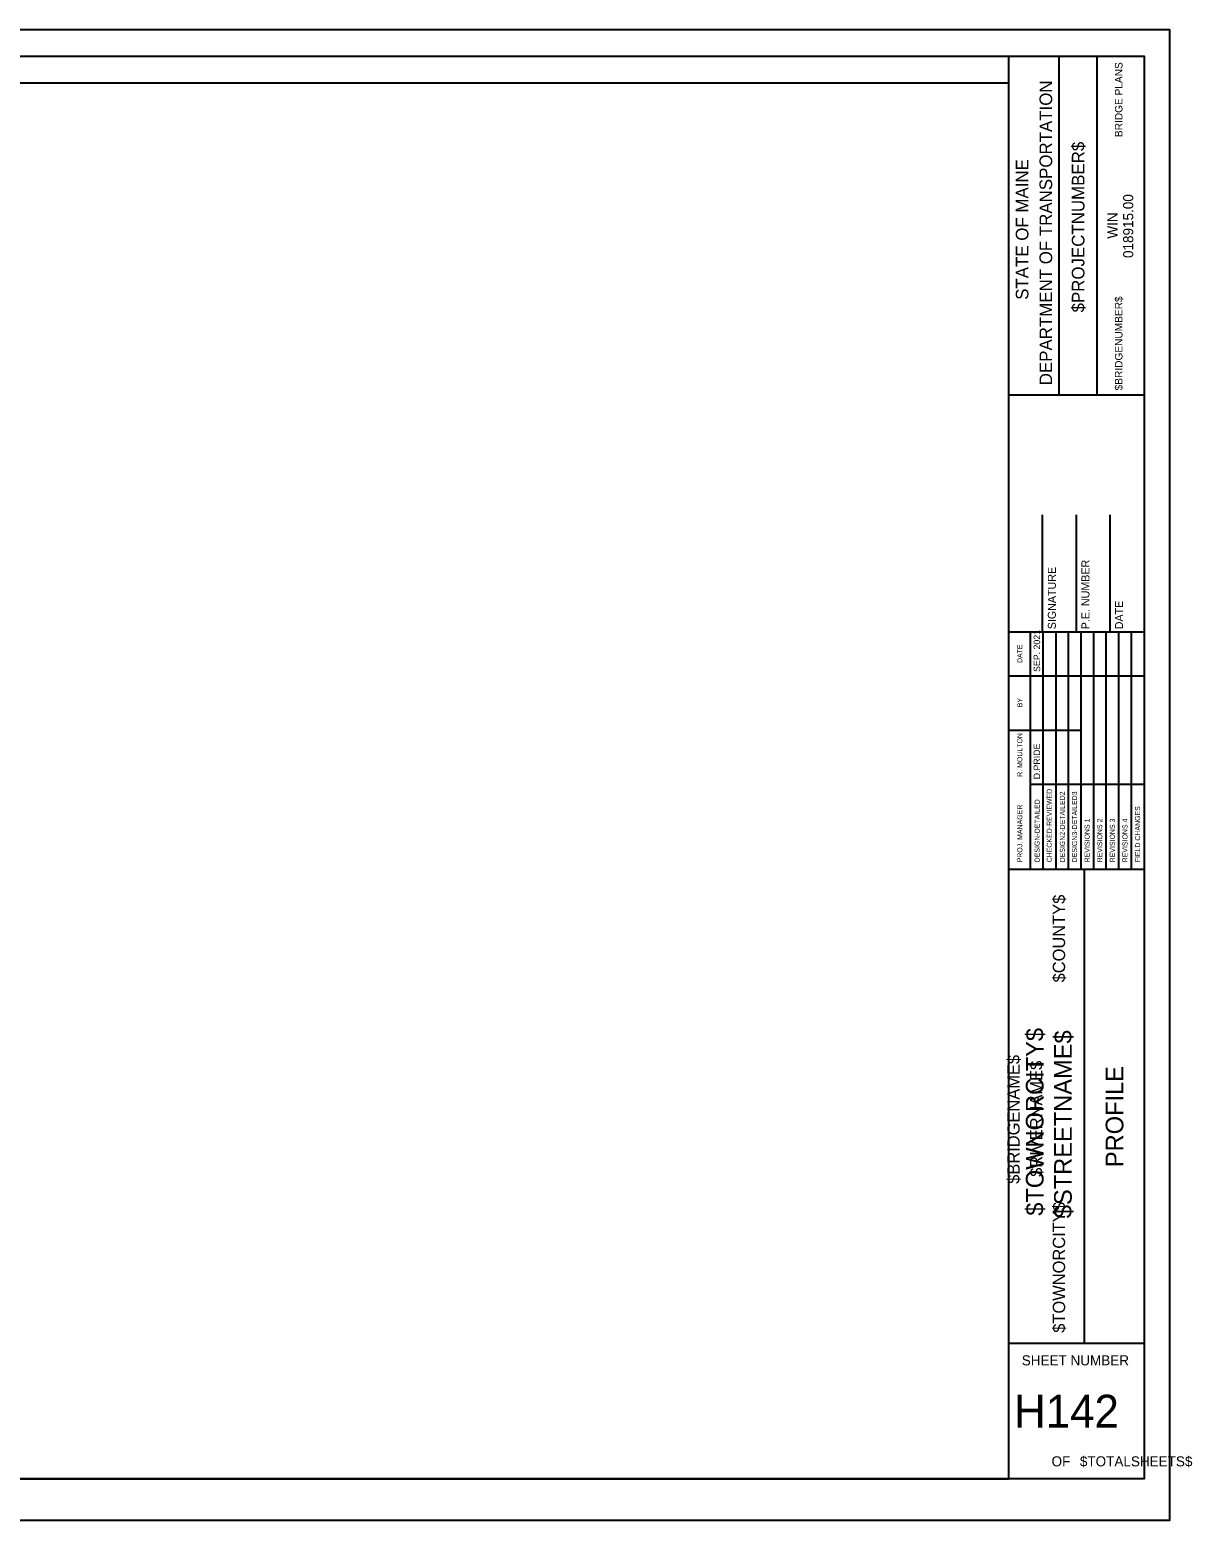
# Model space of a CAD drawing. Extents: x 11800 to 12658, y 9985 to 10535.
# Drawn here: x 12229 to 12658, y 9985 to 10535 of the extents above; entities that cross this region are included whole.
import ezdxf

# ---------------------------------------------------------------- set-up
doc = ezdxf.new("R2010")
doc.units = 0
for name, color, linetype in [('BORDER', 7, 'Continuous'), ('BRIDGE_TITLE', 7, 'Continuous'), ('CLIPS', 7, 'Continuous'), ('HIGHWAY_TITLE', 7, 'Continuous'), ('PLOT BOUNDARY', 7, 'Continuous')]:
    doc.layers.add(name, color=color, linetype=linetype)

msp = doc.modelspace()

# ---------------------------------------------------------------- linework, layer by layer
at = {"layer": 'BORDER'}
for p, q in [((12590.42, 10000), (12590.42, 10525)), ((12609.06, 10399.99), (12609.06, 10524.99)), ((12623.03, 10399.99), (12623.03, 10524.99)), ((12590.42, 10399.97), (12640.42, 10399.97)), ((12602.92, 10312.51), (12602.92, 10355.75)), ((12615.42, 10312.51), (12615.42, 10355.75)), ((12627.92, 10312.51), (12627.92, 10355.75)), ((12590.42, 10312.51), (12640.42, 10312.51)), ((12590.42, 10225.01), (12640.42, 10225.01)), ((12618.37, 10050.01), (12618.37, 10225.01)), ((12590.42, 10050.01), (12640.42, 10050.01))]:
    msp.add_line(p, q, dxfattribs=at)
msp.add_lwpolyline([(11840.42, 10525), (12640.42, 10525), (12640.42, 10000), (11840.42, 10000)], close=True, dxfattribs=at)
for points in [[(12598.49, 10296.26), (12598.49, 10312.51)], [(12603.15, 10225.03), (12603.15, 10312.51)], [(12607.81, 10312.51), (12607.81, 10225.03)], [(12612.47, 10225.03), (12612.47, 10312.51)], [(12617.13, 10225.03), (12617.13, 10312.51)], [(12621.79, 10225.03), (12621.79, 10312.51)], [(12626.44, 10225.03), (12626.44, 10312.51)], [(12631.1, 10225.03), (12631.1, 10312.51)], [(12635.76, 10225.03), (12635.76, 10312.51)], [(12598.49, 10225.03), (12598.49, 10308.98)], [(12590.42, 10296.26), (12640.42, 10296.26)], [(12590.42, 10276.26), (12598.49, 10276.26)], [(12598.49, 10276.26), (12617.12, 10276.26)], [(12598.49, 10256.26), (12640.42, 10256.26)]]:
    msp.add_lwpolyline(points, dxfattribs=at)
at = {"layer": 'CLIPS'}
msp.add_lwpolyline([(11840.42, 10000), (12590.42, 10000), (12590.42, 10515), (11840.42, 10515)], close=True, dxfattribs=at)
at = {"layer": 'PLOT BOUNDARY'}
msp.add_lwpolyline([(11799.95, 9984.7), (12649.95, 9984.7), (12649.95, 10534.7), (11799.95, 10534.7)], close=True, dxfattribs=at)

# ---------------------------------------------------------------- texts
at = {"layer": 'BORDER'}
for s, height, rotation, p in [('DEPARTMENT OF TRANSPORTATION', 4.6588, 90, (12606.45, 10403.53)), ('$PROJECTNUMBER$', 4.6588, 90, (12618.38, 10430.4)), ('STATE OF MAINE', 4.6588, 90, (12597.69, 10435.06)), ('018915.00', 3.726, 90, (12636.39, 10450.49)), ('WIN', 3.726, 90, (12630.6, 10457.65)), ('SIGNATURE', 2.953, 90, (12607.82, 10313.48)), ('P.E. NUMBER', 2.9528, 90, (12620.22, 10313.48)), ('DATE', 2.953, 90, (12632.62, 10313.48)), ('SEP. 2021', 2.423, 90, (12602.03, 10297.74)), ('DATE', 1.857, 90, (12595.44, 10301.04)), ('BY', 1.857, 90, (12595.44, 10284.69)), ('R. MOULTON', 1.864, 90, (12595.44, 10259.03)), ('D.PRIDE', 2.423, 90, (12602.03, 10258.13)), ('CHECKED-REVIEWED', 1.8637, 90, (12606.32, 10227.46)), ('DESIGN2-DETAILED2', 1.8637, 90, (12611.17, 10227.46)), ('DESIGN3-DETAILED3', 1.8637, 90, (12615.64, 10227.46)), ('PROJ. MANAGER', 1.8637, 90, (12595.44, 10227.46)), ('DESIGN-DETAILED', 1.8637, 90, (12601.85, 10227.46)), ('FIELD CHANGES', 1.8637, 90, (12638.93, 10227.46)), ('REVISIONS 1', 1.8637, 90, (12620.3, 10227.46)), ('REVISIONS 2', 1.8637, 90, (12624.95, 10227.46)), ('REVISIONS 3', 1.8637, 90, (12629.61, 10227.46)), ('REVISIONS 4', 1.8637, 90, (12634.27, 10227.46)), ('PROFILE', 6.521, 90, (12632.74, 10115)), ('SHEET NUMBER', 3.7264, 360, (12595.24, 10041.83)), ('OF', 3.726, 360, (12606.25, 10004.56)), ('$TOTALSHEETS$', 3.7264, 360, (12616.7, 10004.56))]:
    msp.add_text(s, height=height, rotation=rotation, dxfattribs=at).set_placement(p)
msp.add_text('H142', height=12.097, dxfattribs=at).set_placement((12592.42, 10018.91))
at = {"layer": 'BRIDGE_TITLE'}
for s, height, p in [('BRIDGE PLANS', 2.795, (12632.42, 10495.12)), ('$BRIDGENUMBER$', 2.795, (12632.42, 10401.65)), ('$COUNTY$', 4.536, (12611.23, 10183.17)), ('$BRIDGENAME$', 4.5358, (12594.46, 10108.86)), ('$RIVERNAME$', 4.5358, (12602.85, 10111.43)), ('$TOWNORCITY$', 4.5358, (12611.23, 10053.88))]:
    msp.add_text(s, height=height, rotation=90, dxfattribs=at).set_placement(p)
at = {"layer": 'HIGHWAY_TITLE'}
for s, p in [('$TOWNORCITY$', (12603.28, 10097.06)), ('$STREETNAME$', (12613.71, 10096.16))]:
    msp.add_text(s, height=6.5214, rotation=90, dxfattribs=at).set_placement(p)

doc.saveas('drawing.dxf')
